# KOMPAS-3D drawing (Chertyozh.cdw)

Views: Вид 1, Вид 2
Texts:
  КП 13.02.11 ЭО-20 2023
  План питающей сети цеха и распределительной сети участка
  User
  Noncommercial version
  а-номер по планировки
  б-установленная мощность, кВт,кВА
  с-ток расцепителя, А
  д-номинальный расчетный ток, А
  - Шинопроводы на кранштейнах
  - Шинопроводы на стойках
  - Тролейные линии
  ВВ1
  Кожух
  Шкаф ввода
  КРН-5
  КН-4
  Секционный
  шкаф-КН3
  СБ (3 70)
  М1-4-ШМА-4-1250
  М2-4-ШМА-4-1250
  Кран G-5т
  ТСЗА 630 10
  ВА51-35  250 250
  ДМС2-015Н
  М1-1ШРА-4-250
  М1-2ШРА-4-250
  ВА51-35  250 160
  УКМ-0,4-240-20
  УКМ-0,4-180-20
  ВА51-37  400 400
  ВА51-37  400 320
  М1-3ШРА-4-250
  М2-4ШРА-4-250
  М2-5ШРА-4-250
  М2-6ШРА-4-250
  Установленная
  мощность Pн
  кВт, кВа
  Расчётный
  ток Iм, А
  ВА51-35 250 250
  ВА51-31 320 250
  ВА51-35 250 160
  Аппарат защиты
  ВА51-31 400 400
  Прессы
  Стыковые сварочные
  машины
  План питающей сети цеха
  и распределительной сети
  участка
  .Сомов С.О.
  Погодина К.В..
Dimensions and other numbers on the sheet: 6000; 12; 11; 10; 9; 8; 7; 6; 5; 4; 3; 1; 72000; 12000; 48000; 259,5; 221,9; 245,3; 219,1; 245,81; 343; 167,9; 367,6; 203,6; 206,1; 273,5; 140,7; 365; 172,3; 183,4; 249; 13; 2; 200; 160; 159,87; 22; 50; 41,5; 150; 125; 119,9; 16; 30; 43,23; 20; 31,5; 28,82; 17; 18; 19; 14; 63; 55,4; 15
